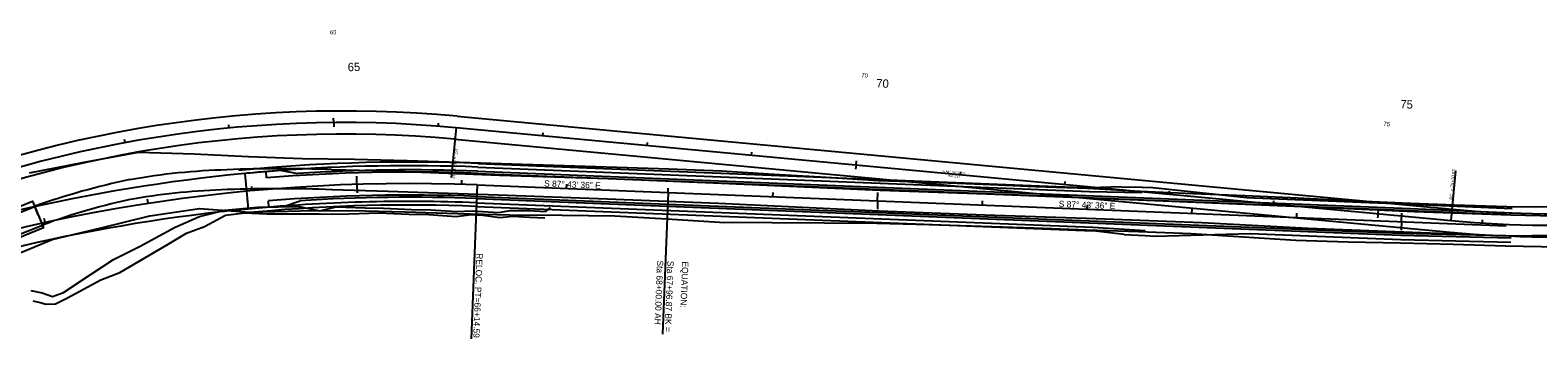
# Model space of a CAD drawing. Extents: x 1965724 to 1970316, y 1117080 to 1118173.
# Drawn here: x 1967871 to 1969309, y 1117777 to 1118071 of the extents above; entities that cross this region are included whole.
import ezdxf

# ---------------------------------------------------------------- set-up
doc = ezdxf.new("R2010")
doc.units = 0
for name, color, linetype in [('RD_EX_Bridge', 7, 'Continuous'), ('RD_EX_H2O_WetLd', 7, 'Continuous'), ('RD_EX_Road', 7, 'Continuous'), ('RD_EX_RW', 7, 'Continuous'), ('RD_HC_CL', 7, 'Continuous'), ('RD_HC_CL_Rel', 7, 'Continuous'), ('RD_HC_Data', 7, 'Continuous'), ('RD_HC_Data_Rel', 7, 'Continuous'), ('RD_HC_Data_Tic_Rel', 7, 'Continuous'), ('RD_HC_TX_Rel_Sta50', 7, 'Continuous'), ('RD_HC_TX_Sta20', 7, 'Continuous'), ('RD_PD_Bridge', 7, 'Continuous'), ('RD_PD_EarthShd', 7, 'Continuous'), ('RD_PD_Final_TrvlWay', 7, 'Continuous'), ('RD_PD_PaveShd', 7, 'Continuous'), ('RD_Sketch3', 7, 'Continuous'), ('RD_Sketch4', 7, 'Continuous')]:
    doc.layers.add(name, color=color, linetype=linetype)

msp = doc.modelspace()

# ---------------------------------------------------------------- linework, layer by layer
at = {"layer": 'RD_EX_Bridge'}
msp.add_lwpolyline([(1967693.2, 1117834.7), (1967873.6, 1117908.4), (1967884, 1117883.1), (1967703.5, 1117809.4), (1967693.2, 1117834.7)], dxfattribs=at)
at = {"layer": 'RD_EX_H2O_WetLd'}
for points in [[(1967871.9, 1117823.2), (1967882.8, 1117820.9), (1967892.5, 1117817.6), (1967903.1, 1117821.5), (1967929.3, 1117838.9), (1967950.7, 1117852.8), (1967976.1, 1117865.5), (1968009.4, 1117883.8), (1968032.7, 1117893.9), (1968056.9, 1117900), (1968088, 1117902.7), (1968127.8, 1117903.4), (1968147.6, 1117899.3), (1968163.2, 1117903), (1968190.6, 1117902.2), (1968208.2, 1117901.8), (1968234.8, 1117900.5), (1968253.3, 1117900.1), (1968277.7, 1117898.7), (1968292.9, 1117899.1), (1968318.2, 1117897.5), (1968328.9, 1117899.6), (1968347.3, 1117899.5), (1968363, 1117898.5), (1968367.5, 1117902.4)], [(1967871.9, 1117823.2), (1967882.8, 1117820.9), (1967892.5, 1117817.6), (1967903.1, 1117821.5), (1967929.3, 1117838.9), (1967950.7, 1117852.8), (1967976.1, 1117865.5), (1968009.4, 1117883.8), (1968032.7, 1117893.9), (1968056.9, 1117900), (1968088, 1117902.7), (1968127.8, 1117903.4), (1968147.6, 1117899.3), (1968163.2, 1117903), (1968190.6, 1117902.2), (1968208.2, 1117901.8), (1968234.8, 1117900.5), (1968253.3, 1117900.1), (1968277.7, 1117898.7), (1968292.9, 1117899.1), (1968318.2, 1117897.5), (1968328.9, 1117899.6), (1968347.3, 1117899.5), (1968363, 1117898.5), (1968367.5, 1117902.4)], [(1967873.8, 1117813.3), (1967880.7, 1117811.8), (1967886.5, 1117810.1), (1967895.5, 1117810.6), (1967906.3, 1117816.1), (1967938.7, 1117833.6), (1967956.7, 1117840.5), (1967984.4, 1117856.8), (1968002.9, 1117867.5), (1968020.4, 1117877.9), (1968037.5, 1117884.2), (1968057.4, 1117895.2), (1968076, 1117897.2), (1968097, 1117896.5), (1968127.6, 1117896.5), (1968147.3, 1117896.5), (1968165.5, 1117895.9), (1968184.9, 1117896.8), (1968203.6, 1117897.4), (1968232.3, 1117895.9), (1968251.4, 1117895.6), (1968277.5, 1117893.8), (1968292.3, 1117895.6), (1968302.8, 1117895.1), (1968319.2, 1117892.9), (1968331.6, 1117894.1), (1968347.7, 1117893.2), (1968362, 1117892.5)], [(1967873.8, 1117813.3), (1967880.7, 1117811.8), (1967886.5, 1117810.1), (1967895.5, 1117810.6), (1967906.3, 1117816.1), (1967938.7, 1117833.6), (1967956.7, 1117840.5), (1967984.4, 1117856.8), (1968002.9, 1117867.5), (1968020.4, 1117877.9), (1968037.5, 1117884.2), (1968057.4, 1117895.2), (1968076, 1117897.2), (1968097, 1117896.5), (1968127.6, 1117896.5), (1968147.3, 1117896.5), (1968165.5, 1117895.9), (1968184.9, 1117896.8), (1968203.6, 1117897.4), (1968232.3, 1117895.9), (1968251.4, 1117895.6), (1968277.5, 1117893.8), (1968292.3, 1117895.6), (1968302.8, 1117895.1), (1968319.2, 1117892.9), (1968331.6, 1117894.1), (1968347.7, 1117893.2), (1968362, 1117892.5)]]:
    msp.add_lwpolyline(points, dxfattribs=at)
at = {"layer": 'RD_EX_Road'}
for p, q in [((1967694.4, 1117831.2), (1967875.7, 1117903.5)), ((1967701.6, 1117814), (1967883.1, 1117885.6))]:
    msp.add_line(p, q, dxfattribs=at)
for points in [[(1969282.9, 1117875.4), (1969323.9, 1117876.1), (1969374.9, 1117877.1), (1969422.8, 1117880.6), (1969473.4, 1117886.6), (1969522.6, 1117895.5), (1969570.2, 1117905.2), (1969616.1, 1117916.1), (1969665.8, 1117928.6), (1969710.9, 1117940.6), (1969757.1, 1117953.2), (1969805.3, 1117966.7), (1969852.3, 1117979.8), (1969901.9, 1117994.1), (1969962.3, 1118013)], [(1969283.3, 1117895.4), (1969325.6, 1117894.4), (1969373.8, 1117895.6), (1969422.2, 1117898.6), (1969472.1, 1117904.7), (1969518.5, 1117913.1), (1969565.2, 1117925.2), (1969612.4, 1117936.1), (1969659.1, 1117947.3), (1969705.6, 1117959), (1969751.6, 1117971.4), (1969799.2, 1117984.2), (1969810.8, 1117987.5)], [(1968158.7, 1117938.6), (1968212.1, 1117937.2), (1968318.8, 1117933.3), (1968422.8, 1117929.9), (1968530.5, 1117925.7)], [(1968158.7, 1117938.6), (1968212.1, 1117937.2), (1968318.8, 1117933.3), (1968422.8, 1117929.9), (1968530.5, 1117925.7)], [(1968530.5, 1117925.7), (1968682, 1117919), (1968783.2, 1117915.4), (1968888.6, 1117911.4), (1968991.2, 1117907.1), (1969092, 1117903.1), (1969191.1, 1117898.7), (1969283.3, 1117895.4)], [(1968530.5, 1117925.7), (1968682, 1117919), (1968783.2, 1117915.4), (1968888.6, 1117911.4), (1968991.2, 1117907.1), (1969092, 1117903.1), (1969191.1, 1117898.7), (1969283.3, 1117895.4)], [(1968159.2, 1117919.4), (1968212.5, 1117918), (1968317.5, 1117914.4), (1968421.5, 1117910.8), (1968527.8, 1117906.4)], [(1968159.2, 1117919.4), (1968212.5, 1117918), (1968317.5, 1117914.4), (1968421.5, 1117910.8), (1968527.8, 1117906.4)], [(1967879, 1117895.5), (1967875.7, 1117903.5)], [(1967879, 1117895.5), (1967883.1, 1117885.6)], [(1968527.8, 1117906.4), (1968680.8, 1117899.1), (1968781.7, 1117895.4), (1968887.9, 1117891.8), (1968988.7, 1117888.2), (1969090.1, 1117882.8), (1969189.3, 1117879), (1969282.9, 1117875.4)], [(1968527.8, 1117906.4), (1968680.8, 1117899.1), (1968781.7, 1117895.4), (1968887.9, 1117891.8), (1968988.7, 1117888.2), (1969090.1, 1117882.8), (1969189.3, 1117879), (1969282.9, 1117875.4)]]:
    msp.add_lwpolyline(points, dxfattribs=at)
for centre, radius, start, end in [((1968075.1, 1117320.6), 617.9, 91.4965, 100.1295), ((1968075.1, 1117320.6), 617.9, 91.4965, 100.1295), ((1968111.4, 1116608.6), 1330.8, 87.9632, 92.259), ((1968111.4, 1116608.6), 1330.8, 87.9632, 92.259), ((1968104.9, 1117261.1), 682.1, 101.7162, 109.6396), ((1968104.9, 1117261.1), 682.1, 101.7162, 109.6396), ((1968080.6, 1117363), 558.7, 101.3479, 110.7006), ((1968080.6, 1117363), 558.7, 101.3479, 110.7006), ((1968080.7, 1117246.5), 673.3, 91.837, 99.4057), ((1968080.7, 1117246.5), 673.3, 91.837, 99.4057), ((1968107.6, 1116504.3), 1416, 87.9115, 91.9598), ((1968107.6, 1116504.3), 1416, 87.9115, 91.9598)]:
    msp.add_arc(centre, radius, start, end, dxfattribs=at)
at = {"layer": 'RD_EX_RW'}
for points in [[(1967870.6, 1117935.4), (1967922.7, 1117945.6), (1967974.5, 1117955.3), (1968027.5, 1117953.6), (1968079.5, 1117951), (1968130.7, 1117949), (1968180.7, 1117948.4), (1968230.7, 1117947.1), (1968280.6, 1117945.5), (1968330.6, 1117944), (1968380.6, 1117942.5), (1968430.6, 1117940.9), (1968480.5, 1117939.1), (1968530.5, 1117937.2), (1968580.4, 1117934.2), (1968630.3, 1117931.2), (1968680.3, 1117928.2), (1968730.2, 1117926.4), (1968780.2, 1117924.7), (1968830.1, 1117922.4), (1968880.1, 1117920.9), (1968930, 1117917.9), (1968980, 1117915.8), (1969030, 1117913.7), (1969079.9, 1117911.5), (1969129.9, 1117909.2), (1969179.8, 1117906.8), (1969229.8, 1117904.9), (1969279.7, 1117903.2)], [(1969279.7, 1117903.2), (1969328.8, 1117903.1), (1969377.9, 1117904.1), (1969426.9, 1117907.6), (1969475.5, 1117914.7), (1969524.1, 1117922.3), (1969572.1, 1117933.1)], [(1967708.8, 1117795.8), (1967892.1, 1117872), (1967938.9, 1117882.9), (1967985.3, 1117894.6), (1968032.7, 1117901.4), (1968080.7, 1117898.1), (1968128.7, 1117899.3), (1968178.7, 1117899.4), (1968228.7, 1117898.2), (1968278.7, 1117896.8), (1968328.7, 1117895.5), (1968378.7, 1117895.2), (1968428.7, 1117894.5), (1968478.6, 1117891.5), (1968528.6, 1117888.4), (1968578.6, 1117888), (1968628.6, 1117887.7), (1968678.6, 1117887.4), (1968728.6, 1117886.1), (1968778.6, 1117884.7), (1968828.6, 1117882.9), (1968878.6, 1117881.2), (1968928.5, 1117879.4), (1968978.5, 1117877.6), (1969028.4, 1117874.5), (1969078.3, 1117871.2), (1969128.3, 1117869.8), (1969178.3, 1117868.8), (1969228.3, 1117867.4), (1969278.3, 1117865.8), (1969329.2, 1117864.9)]]:
    msp.add_lwpolyline(points, dxfattribs=at)
at = {"layer": 'RD_HC_CL'}
msp.add_line((1968277.4, 1117978.5), (1969226.4, 1117889.9), dxfattribs=at)
for centre, radius, start, end in [((1968170.8, 1116837.5), 1145.9, 84.6661, 115.0463), ((1969323.3, 1118927.1), 1041.7, 264.6661, 284.1493)]:
    msp.add_arc(centre, radius, start, end, dxfattribs=at)
at = {"layer": 'RD_HC_CL_Rel'}
for p, q in [((1968297.5, 1117923.9), (1968479.6, 1117916.7)), ((1968479.6, 1117916.7), (1969279, 1117884.9))]:
    msp.add_line(p, q, dxfattribs=at)
msp.add_arc((1968232.6, 1116288.2), 1637, 87.7266, 111.9958, dxfattribs=at)
at = {"layer": 'RD_HC_Data'}
for p, q in [((1968060.9, 1117978.1), (1968060.6, 1117981.1)), ((1968160.7, 1117983.4), (1968160.6, 1117987.4)), ((1968160.7, 1117983.4), (1968160.7, 1117979.4)), ((1968260.6, 1117979.9), (1968260.8, 1117982.9)), ((1967961.9, 1117964.2), (1967961.3, 1117967.2)), ((1968277.4, 1117978.5), (1968272.9, 1117931.1)), ((1968360.2, 1117970.7), (1968360.4, 1117973.7)), ((1968459.7, 1117961.4), (1968460, 1117964.4)), ((1968559.3, 1117952.1), (1968559.6, 1117955.1)), ((1968658.9, 1117942.8), (1968658.5, 1117938.9)), ((1968658.9, 1117942.8), (1968659.2, 1117946.8)), ((1968758.4, 1117933.5), (1968758.7, 1117936.5)), ((1968858, 1117924.3), (1968858.3, 1117927.2)), ((1969226.4, 1117889.9), (1969230.9, 1117937.3)), ((1968957.6, 1117915), (1968957.8, 1117917.9)), ((1969057.1, 1117905.7), (1969057.4, 1117908.6)), ((1969156.7, 1117896.4), (1969156.3, 1117892.4)), ((1969156.7, 1117896.4), (1969157.1, 1117900.3)), ((1969256.3, 1117887.5), (1969256.5, 1117890.5))]:
    msp.add_line(p, q, dxfattribs=at)
at = {"layer": 'RD_HC_Data_Rel'}
for p, q in [((1968297.5, 1117923.9), (1968291.7, 1117777.2)), ((1968479.6, 1117916.7), (1968474.3, 1117781.6))]:
    msp.add_line(p, q, dxfattribs=at)
at = {"layer": 'RD_HC_Data_Tic_Rel'}
for p, q in [((1968182.9, 1117924.4), (1968182.7, 1117932.4)), ((1968182.9, 1117924.4), (1968183.2, 1117916.5)), ((1968282.9, 1117924.4), (1968283, 1117928.4)), ((1968382.8, 1117920.5), (1968383, 1117924.5)), ((1967983.9, 1117906.2), (1967983.3, 1117910.2)), ((1968083.1, 1117918.4), (1968082.8, 1117922.3)), ((1968479.6, 1117916.7), (1968479.8, 1117920.7)), ((1968579.6, 1117912.7), (1968579.7, 1117916.7)), ((1968679.5, 1117908.7), (1968679.8, 1117916.7)), ((1968679.5, 1117908.7), (1968679.2, 1117900.8)), ((1968779.4, 1117904.8), (1968779.6, 1117908.8)), ((1968879.3, 1117900.8), (1968879.5, 1117904.8)), ((1968979.3, 1117896.8), (1968979.4, 1117900.8)), ((1969079.2, 1117892.9), (1969079.3, 1117896.9)), ((1969179.1, 1117888.9), (1969179.4, 1117896.9)), ((1967885.6, 1117888), (1967884.7, 1117891.9)), ((1969179.1, 1117888.9), (1969178.8, 1117880.9))]:
    msp.add_line(p, q, dxfattribs=at)
at = {"layer": 'RD_PD_Bridge'}
msp.add_line((1968076.1, 1117934.8), (1968079.3, 1117900.9), dxfattribs=at)
for radius in [1654, 1620]:
    msp.add_arc((1968232.6, 1116288.2), radius, 95.4299, 110.8299, dxfattribs=at)
at = {"layer": 'RD_PD_EarthShd'}
for p, q in [((1968298.3, 1117944.4), (1968881.8, 1117921.2)), ((1968911.8, 1117922.1), (1968881.8, 1117921.2)), ((1968911.8, 1117922.1), (1968931.8, 1117921.7)), ((1968931.8, 1117921.7), (1968941.8, 1117921.4)), ((1968941.8, 1117921.4), (1969031.5, 1117911.8)), ((1969031.5, 1117911.8), (1969179.8, 1117905.9)), ((1969038.7, 1117911.5), (1969179.8, 1117905.9)), ((1968296.7, 1117903.4), (1968884.7, 1117880.1)), ((1969179.8, 1117905.9), (1969284.7, 1117901.3)), ((1968914.6, 1117876.8), (1968884.7, 1117880.1)), ((1968914.6, 1117876.8), (1968934.5, 1117875.6)), ((1968934.5, 1117875.6), (1968944.5, 1117875.2)), ((1968944.5, 1117875.2), (1969034.7, 1117877.6)), ((1969034.7, 1117877.6), (1969178.4, 1117871.9)), ((1969178.5, 1117871.9), (1969283.5, 1117869.5))]:
    msp.add_line(p, q, dxfattribs=at)
for radius, start, end in [(1657.5, 95.1349, 95.6373), (1657.5, 87.7266, 95.1349), (1616.5, 95.1122, 95.6426), (1616.5, 87.7266, 95.1122)]:
    msp.add_arc((1968232.6, 1116288.2), radius, start, end, dxfattribs=at)
at = {"layer": 'RD_PD_Final_TrvlWay'}
for p, q in [((1968278.4, 1117989.4), (1969227.5, 1117900.8)), ((1968276.3, 1117967.5), (1969225.4, 1117878.9)), ((1968096.7, 1117930.6), (1968096.2, 1117936.6)), ((1968297.9, 1117934.9), (1968480.1, 1117927.7)), ((1968480.1, 1117927.7), (1969179.5, 1117899.9)), ((1968297.1, 1117912.9), (1968479.2, 1117905.7)), ((1968099, 1117902.7), (1968098.5, 1117908.7)), ((1968479.2, 1117905.7), (1969178.7, 1117877.9)), ((1969179.5, 1117899.9), (1969279.4, 1117895.6)), ((1969178.7, 1117877.9), (1969278.6, 1117875.6))]:
    msp.add_line(p, q, dxfattribs=at)
for centre, radius, start, end in [((1968170.8, 1116837.5), 1156.9, 84.6661, 115.0463), ((1968170.8, 1116837.5), 1134.9, 84.6661, 115.0463), ((1968232.6, 1116288.2), 1654, 94.7299, 95.4299), ((1968232.6, 1116288.2), 1648, 87.7266, 94.7299), ((1969323.3, 1118927.1), 1030.7, 264.6661, 284.1493), ((1968232.6, 1116288.2), 1626, 87.7266, 94.7299), ((1968232.6, 1116288.2), 1620, 94.7299, 95.4299), ((1969323.3, 1118927.1), 1052.7, 264.6661, 284.1493)]:
    msp.add_arc(centre, radius, start, end, dxfattribs=at)
at = {"layer": 'RD_PD_PaveShd'}
for p, q in [((1968111.1, 1117937.7), (1968126.4, 1117934.8)), ((1968298, 1117936.9), (1968480.2, 1117929.7)), ((1968480.2, 1117929.7), (1969179.6, 1117901.9)), ((1968113.9, 1117903.8), (1968128.6, 1117908.9)), ((1968297, 1117910.9), (1968479.1, 1117903.7)), ((1968479.1, 1117903.7), (1969178.6, 1117875.9)), ((1969179.6, 1117901.9), (1969284.5, 1117897.3)), ((1969178.6, 1117875.9), (1969283.6, 1117873.5))]:
    msp.add_line(p, q, dxfattribs=at)
for radius, start, end in [(1654, 94.2103, 95.4299), (1650, 87.7266, 93.6882), (1624, 87.7266, 93.6715), (1620, 94.1994, 95.4299)]:
    msp.add_arc((1968232.6, 1116288.2), radius, start, end, dxfattribs=at)
at = {"layer": 'RD_Sketch3'}
for p, q in [((1968296.8, 1117906.9), (1968884.8, 1117883.6)), ((1968884.8, 1117883.6), (1968934.7, 1117880.6))]:
    msp.add_line(p, q, dxfattribs=at)
for start, end in [(95.1122, 96.3942), (87.7266, 95.4299)]:
    msp.add_arc((1968232.6, 1116288.2), 1620, start, end, dxfattribs=at)
at = {"layer": 'RD_Sketch4'}
for p, q in [((1968298.2, 1117940.9), (1968881.6, 1117917.7)), ((1968881.6, 1117917.7), (1968931.6, 1117916.8))]:
    msp.add_line(p, q, dxfattribs=at)
for start, end in [(87.7266, 94.3474), (94.3474, 95.4299)]:
    msp.add_arc((1968232.6, 1116288.2), 1654, start, end, dxfattribs=at)

# ---------------------------------------------------------------- texts
at = {"layer": 'RD_HC_Data'}
for s, height, rotation, p in [('PT  = 66+16.82', 3, 264.6661, (1968276, 1117958.5)), ('S 84%%d 39\' 58" E', 2.4, 354.6661, (1968741.1, 1117935.7)), ('PC  = 75+70.03', 3, 84.6661, (1969227.8, 1117909.8)), ('953.211', 2.4, 354.6661, (1968746.1, 1117931.8))]:
    msp.add_text(s, height=height, rotation=rotation, dxfattribs=at).set_placement(p)
at = {"layer": 'RD_HC_Data_Rel'}
for s, rotation, p in [('S 87%%d 43\' 36" E', 357.7266, (1968361.3, 1117922.4)), ('S 87%%d 43\' 36" E', 357.7266, (1968852.1, 1117902.9)), ('RELOC. PT=66+14.59', 267.7266, (1968296.9, 1117858.9)), ('Sta 68+00.00 AH', 267.7266, (1968469.1, 1117852)), ('Sta 67+96.87 BK = ', 267.7266, (1968479.1, 1117851.7)), ('EQUATION:', 267.7266, (1968493.1, 1117851.1))]:
    msp.add_text(s, height=6, rotation=rotation, dxfattribs=at).set_placement(p)
at = {"layer": 'RD_HC_TX_Rel_Sta50'}
for s, rotation, p in [('65', 1.7374, (1968174.2, 1118032.2)), ('70', 357.7266, (1968678.1, 1118016.9)), ('75', 357.7266, (1969177.9, 1117997))]:
    msp.add_text(s, height=8, rotation=rotation, dxfattribs=at).set_placement(p)
at = {"layer": 'RD_HC_TX_Sta20'}
for s, rotation, p in [('65', 0.5072, (1968157.2, 1118067.4)), ('70', 354.6661, (1968663.9, 1118026.7)), ('75', 354.6661, (1969161.8, 1117980.3))]:
    msp.add_text(s, height=4, rotation=rotation, dxfattribs=at).set_placement(p)

doc.saveas('drawing.dxf')
